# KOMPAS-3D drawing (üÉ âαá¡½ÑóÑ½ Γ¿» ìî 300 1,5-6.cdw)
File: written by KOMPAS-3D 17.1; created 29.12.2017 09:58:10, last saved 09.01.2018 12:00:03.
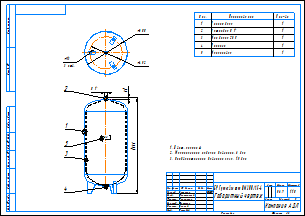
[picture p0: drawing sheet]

Sheet 1: A3, landscape, title-block layout from C:\Лощинин\GRAPHIC.LYT style 1

Title block, sheet 1: name: БР Гранлевел тип НМ 300/1,5-6 / Габаритный чертеж; mass: 56,9; sheets: 1; sheet format: A3; stored path: \\Fsk1\files\АП\20_PKO\02_Насосное направление\Разработка\04_Проекты разные\Баки\КД действующая\Баки Flexcon R\Компас\Чертежи\БР Гранлевел тип НМ 300 1,5-6.cdw; drawn by: Лощинин; checked by: Хантимеров; drawn by, date: 29.12.2017

Views: Проекционный вид 2
Referenced files in \\Fsk1\files\АП\20_PKO\02_Насосное направление\Разработка\04_Проекты разные\Баки\КД действующая\Баки Flexcon R\Компас\: 300 литров.a3d, 16302_Flexcon_300_1-6.m3d
Referenced files in C:\Лощинин\: GRAPHIC.LYT
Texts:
  IvAn
  ADL
  Поз.
  Кол-во
  Корпус бака
  Мембрана SBR
  Патрубок G 1"
  Ниппель
  Маркировка
  АДЛ
  Цвет: красный
  Максимальное рабочее давление: 6 бар
  Предварительное давление газа: 1,5 бар
  ACAD_ISO03W100_RGB_223_127_255_SC_0.063_THICK_0.05
  ACAD_ISO03W100_RGB_223_127_255_SC_1_THICK_0.05
  Лит-Масса-Масштаб
  Материал-Предприятие
  Масштаб
  Изм.
  Лист
  № докум.
  Подп.
  Дата
  Лит.
  Разраб.
  Пров.
  Т.контр.
  Курлыкина
  Листов
  Нач.отд.
  Щетинин
  Н.контр.
  Долгов
  Утв.
  Рашидов
  Компания АДЛ
  Изменение
  Номер документа
  Подпись
  Обозначение документа
  Наименование изделия
  Масса изделия по ГОСТ 2.109-73
  Порядковый номер листа
  Общее количество листов в документе
  Характер работы, выполненной лицом, подписавшим документ
  Наименование или индекс предприятия, выпускающего документ
  Инв. № подл.
  Подп. и дата
  Взам. инв. №
  Инв. № дубл.
  Инвентарный номер подлинника по ГОСТ 2.501-68
  Подпись принявшего подлинник в отдел технической документации
  Инвентарный номер подлинника, взамен которого выпущен данный подлинник
  Инвентарный номер дубликата по ГОСТ 2.502-68
  Подпись принявшего дубликат в отдел технической документации
  Справ. №
  Перв. примен.
  Обозначение документа, взамен или на основании которого выпущен данный документ
  Обозначение документа, в котором впервые записан данный документ
  Подпись лица, копировавшего чертеж
  Обозначение формата листа
Dimensions and other numbers on the sheet: 1; 3; 2; 4; 5; 1330; 21; 1:10; 56,9; 29.12.2017; 16302_Flexcon_300_1-6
